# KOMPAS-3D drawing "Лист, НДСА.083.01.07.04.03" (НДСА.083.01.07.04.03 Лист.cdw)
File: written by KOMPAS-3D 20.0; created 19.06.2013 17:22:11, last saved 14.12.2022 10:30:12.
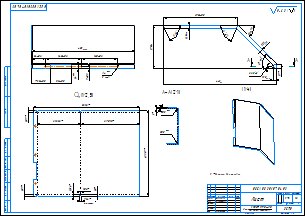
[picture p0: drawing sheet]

Sheet 1: A2, landscape

Document properties: Автор: Шубников; Знак неуказанной шероховатости: 4; Параметр неуказанной шероховатости: Ra6.3; Полное имя файла: НДСА.083.01.07.04.03 Лист.m3d; PLM_CDWXDTO: <item xmlns="http://appius.ru/pdm" xmlns:xs="http://www.w3.org/2001/XMLSchema" xmlns:xsi="http://www.w3.org/2001/XMLSchema-instance" xsi:type="item">  <element xmlns:d2p1="http://v8.1c.ru/8.1/data/enterprise/current-config" xsi:type="d2p1:CatalogRef.aps_Элемен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; Масса: 1.72156; PDM_DOCXDTO: <item xmlns="http://appius.ru/pdm" xmlns:xs="http://www.w3.org/2001/XMLSchema" xmlns:xsi="http://www.w3.org/2001/XMLSchema-instance" xsi:type="item">  <element xmlns:d2p1="http://v8.1c.ru/8.1/data/enterprise/current-config" xsi:type="d2p1:CatalogRef.aps_Элемен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; PDM_ITEMXDTO: <item xmlns="http://appius.ru/pdm" xmlns:xs="http://www.w3.org/2001/XMLSchema" xmlns:xsi="http://www.w3.org/2001/XMLSchema-instance" xsi:type="item">  <element xmlns:d2p1="http://v8.1c.ru/8.1/data/enterprise/current-config" xsi:type="d2p1:CatalogRef.aps_Элемен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; PDM_DRAWINGXDTO: <item xmlns="http://appius.ru/pdm" xmlns:xs="http://www.w3.org/2001/XMLSchema" xmlns:xsi="http://www.w3.org/2001/XMLSchema-instance" xsi:type="item">  <element xmlns:d2p1="http://v8.1c.ru/8.1/data/enterprise/current-config" xsi:type="d2p1:CatalogRef.aps_Элемен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; Организация: ЭСТО-Вакуум

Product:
- Part/product: Лист  | designation НДСА.083.01.07.04.03
    Материал: Лист$d1 ГОСТ 19904-90;10 ГОСТ 16523-97$ (density 7856 kg/m3)
    Масса: 1.72156
    additional columns: <item xmlns="http://appius.ru/pdm" xmlns:xs="http://www.w3.org/2001/XMLSchema" x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; <item xmlns="http://appius.ru/pdm" xmlns:xs="http://www.w3.org/2001/XMLSchema" x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; <item xmlns="http://appius.ru/pdm" xmlns:xs="http://www.w3.org/2001/XMLSchema" x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
    source file: НДСА.083.01.07.04.03 Лист.cdw

Title block, sheet 1: Наименование: Лист; designation: НДСА.083.01.07.04.03; Материал: Лист 1 ГОСТ 19904-90 10 ГОСТ 16523-97; Масса: 1,72; scale: 1:2; Количество листов документа: 1; organisation: ЭСТО; Форматы листов документа: A2; stored path: C:\Пищагина\Чертежи Ялика\УКРД.839.01.06.04.02 - Лист.cdw; Разработал: Щербакова; Проверил: Горностаев; Утвердил: Белецкий; Разработал, date: 14.12.2022

Views: Проекционный вид 2, Разрез А-А, Вид 5, Развертка
Referenced files in C:\Users\cherbakova\Desktop\Виноград\Новая папка (4)\: НДСА.083.01.07.04.03 Лист.m3d
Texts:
  Гл 1
  Пользовательская
  Ra6.3
  Ra6.3 ( )
  НДСА.083.01.07.04.03 Лист
Dimensions and other numbers on the sheet: 403; 73,5±0,5; 83±0,5; 54±0,2; 140±0,2; 16; 9±0,2; 4; 3 отв.; 290±0,5; 11,5; 170; 441; 19; 22,5; 0,5; 1; 11,34; 1,06; 10; 9,34; 4 места; 10,7; 290,12; 212,36; 521,6; 422,67; 1:2; 1,72; 14.12.2022

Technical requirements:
  *Размеры для справок.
